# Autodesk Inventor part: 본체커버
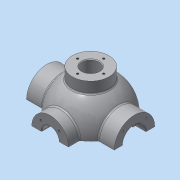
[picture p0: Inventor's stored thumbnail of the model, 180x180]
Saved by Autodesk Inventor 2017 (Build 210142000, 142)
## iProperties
Created: 2015-12
Part Number: 본체커버
Material: 알루미늄 6061
Document SubType Name: Modeling
Designer: mduedu
Density: 2.71 g/cm^3
Mass: 574.083 g
Surface Area: 451.737 cm^2
Volume: 211.839 cm^3
Appearance: 알루미늄 - 평지
Author: mduedu
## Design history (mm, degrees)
sketch "스케치1"
  geometry: L1 (-53, 0)-(53, 0); A1 r 53 centre (0, 0) between (53, 0) and (-53, 0); 2 further points
  constraints: 2 coincident, 2 end point, 2 point on circle, 1 centre point, 1 horizontal, 1 midpoint
  dimensions: "d0" = 53 radius of A1
revolve "회전1" sketch "스케치1" stored, may be unused: angle "d2" = 90 deg
feature "쉘1" dims "d11" = 10
node "작업 평면1"
sketch "스케치2"
  geometry: C1 r 31 at (0, 0); 1 further point
  constraints: 1 centre point, 1 coincident
  dimensions: "d4" = 62 diameter of C1
extrude "돌출1" join sketch "스케치2" stored distance "d5" = 10; taper "d6" = 0 deg
node "작업 평면2"
sketch "스케치3"
  geometry: C1 r 28 at (0, 0); 1 further point
  constraints: 1 centre point, 1 coincident
  dimensions: "d8" = 56 diameter of C1
extrude "돌출2" join sketch "스케치3" stored distance "d9" = 10; taper "d10" = 0 deg
hole "구멍1" diameter "d14" = 35; stored, may be unused: countersink angle "d18" = 90 deg, drill point angle "d20" = 0 deg; dims "d12" = 10, "d13" = 10, "d15" = 6, "d16" = 4, "d17" = 2, "d19" = 16
hole "구멍2" diameter "d23" = 27; stored, may be unused: countersink angle "d27" = 90 deg, drill point angle "d29" = 0 deg; dims "d21" = 10, "d22" = 10, "d24" = 6, "d25" = 4, "d26" = 2, "d28" = 16
fillet "모깎기1" dims "d30" = 0.3
hole "구멍3" diameter "d33" = 26; stored, may be unused: countersink angle "d37" = 90 deg, drill point angle "d39" = 0 deg; dims "d31" = 10, "d32" = 10, "d34" = 6, "d35" = 4, "d36" = 2, "d38" = 16
chamfer "모따기1" distance "d40" = 1; stored, may be unused: second distance "d41" = 2, angle "d42" = 45 deg
sketch "스케치4"
  geometry: L1 (0, 0)-(0, -25); L2 (0, 0)-(-17.678, -17.678); A1 r 25 centre (0, 0) between (-17.678, -17.678) and (0, -25); 1 further point
  constraints: 4 end point, 2 point on circle, 1 centre point, 1 coincident, 1 vertical
  dimensions: "d43" = 50 diameter of A1; "d47" = 45 deg angle of L1 L2
hole "구멍4" sketch "스케치4" at (-17.678, -17.678) diameter "d49" = 3.242; stored, may be unused: countersink angle "d53" = 90 deg, drill point angle "d55" = 118 deg; dims "d50" = 11, "d51" = 4, "d52" = 2, "d54" = 13
sketch "스케치5"
  geometry: L1 (0, 0)-(0, -20); L2 (0, 0)-(-14.142, -14.142); A1 r 20 centre (0, 0) between (0, -20) and (-14.142, -14.142); 2 further points
  constraints: 4 end point, 2 coincident, 2 point on circle, 1 centre point, 1 vertical
  dimensions: "d59" = 40 diameter of A1; "d65" = 45 deg angle of L1 L2
hole "구멍5" sketch "스케치5" at (-14.142, -14.142) diameter "d67" = 3.242; stored, may be unused: countersink angle "d71" = 90 deg, drill point angle "d73" = 118 deg; dims "d68" = 8, "d69" = 4, "d70" = 2, "d72" = 10
node "작업 평면3"
sketch "스케치6"
  geometry: C1 r 65 at (0, 0); 1 further point
  constraints: 1 centre point, 1 coincident
  dimensions: "d78" = 130 diameter of C1
extrude "돌출3" join sketch "스케치6" distance "d80" = 10; taper "d81" = 0 deg
sketch "스케치7"
  geometry: C1 r 20 at (0, 0); 1 further point
  constraints: 1 centre point, 1 coincident
  dimensions: "d82" = 40 diameter of C1
extrude "돌출4" join sketch "스케치7" stored distance "d84" = 10; taper "d85" = 0 deg
sketch "스케치8"
  geometry: 2 further points
  constraints: 1 coincident
hole "구멍6" sketch "스케치8" at (0, 0) diameter "d86" = 20; stored, may be unused: countersink angle "d90" = 90 deg, drill point angle "d92" = 118 deg; dims "d87" = 7, "d88" = 40, "d89" = 5, "d91" = 10
fillet "모깎기2" dims "d93" = 0.3
sketch "스케치9"
  geometry: L1 (65, -75)-(-65, -75) reference; L2 (-45, -75)-(-38.245, -36.692); A1 r 53 centre (0, 0) between (42.988, 31) and (42.988, -31) reference; 1 further point
  constraints: 2 end point, 1 point on circle, 1 point on line
  dimensions: "d94" = 45 horizontal distance of L2.start point (0, 0); "d95" = 80 deg angle of L2 L1
feature "리브1" sketch "스케치9" dims "d96" = 1, "d97" = 8, "d98" = 0, "d99" = 0, "d100" = 1, "d101" = 1
sketch "스케치10"
  geometry: L1 (0, 0)-(0, -55); L2 (0, 0)-(-38.891, -38.891); A1 r 55 centre (0, 0) between (0, -55) and (-38.891, -38.891); 2 further points
  constraints: 4 end point, 2 coincident, 2 point on circle, 1 centre point, 1 vertical
  dimensions: "d105" = 110 diameter of A1; "d107" = 45 deg angle of L1 L2
hole "구멍7" sketch "스케치10" at (-38.891, -38.891) diameter "d109" = 10; stored, may be unused: countersink angle "d113" = 90 deg, drill point angle "d115" = 118 deg; dims "d110" = 7, "d111" = 40, "d112" = 5, "d114" = 10
fillet "모깎기3" dims "d120" = 3
fillet "모깎기4" dims "d121" = 3, "d122" = 3
fillet "모깎기5" dims "d123" = 3
fillet "모깎기6" dims "d124" = 3
sketch "스케치11"
  geometry: C1 r 5 at (-38.891, 38.891) reference; C2 r 5 at (38.891, 38.891) reference; C3 r 5 at (38.891, -38.891) reference; C4 r 5 at (-38.891, -38.891) reference; C5 r 20 at (0, 0) reference; C6 r 65 at (0, 0) reference; 1 further point
  constraints: 3 other
feature "엠보싱1" sketch "스케치11" dims "d125" = 0.5, "d126" = 0
sketch "스케치12"
  geometry: L1 (0, 100)-(0, -100); L2 (0, 100)-(-150, 100); L3 (-150, 100)-(-150, -100); L4 (-150, -100)-(0, -100); 2 further points
  constraints: 8 end point, 3 perpendicular, 1 coincident, 1 midpoint, 1 vertical
  dimensions: "d127" = 200 distance of L2.end L3.end; "d129" = 150 distance of L3.end L1.end
extrude "돌출5" cut sketch "스케치12" stored distance "d130" = 10; taper "d131" = 0 deg
sketch "스케치13"
  geometry: C1 r 7 at (0, -53); A1 r 53 centre (0, 0) between (-42.113, -32.179) and (42.113, -32.179) reference; 1 further point
  constraints: 1 centre point, 1 point on circle
  dimensions: "d132" = 14 diameter of C1
extrude "돌출6" join sketch "스케치13" distance "d133" = 5; taper "d134" = 0 deg
sketch "스케치14"
  geometry: C1 r 7 at (0, 0) reference; 1 further point
extrude "돌출7" cut sketch "스케치14" stored distance "d135" = 5; taper "d136" = 0 deg
sketch "스케치15"
  geometry: C1 r 2.25 at (0, 53); A1 r 7 centre (0, 53) between (6.965, 52.302) and (-6.965, 52.302) reference; 1 further point
  constraints: 1 centre point, 1 coincident
  dimensions: "d139" = 4.5 diameter of C1
extrude "돌출8" cut sketch "스케치15" stored distance "d141" = 5; taper "d142" = 0 deg
fillet "모깎기7" dims "d143" = 3
fillet "모깎기8" dims "d144" = 1
fillet "모깎기9" dims "d145" = 1
fillet "모깎기10" dims "d146" = 1
node "작업 평면4"
sketch "스케치16"
  geometry: C1 r 28 at (0, 0); 1 further point
  constraints: 1 centre point, 1 coincident
  dimensions: "d148" = 56 diameter of C1
extrude "돌출9" join sketch "스케치16" stored distance "d150" = 5; taper "d151" = 0 deg
hole "구멍8" diameter "d154" = 26; stored, may be unused: countersink angle "d158" = 90 deg, drill point angle "d160" = 118 deg; dims "d152" = 10, "d153" = 10, "d155" = 6, "d156" = 4, "d157" = 2, "d159" = 8
sketch "스케치17" dims "d161" = 40
  geometry: 3 further points
  constraints: 2 vertical alignment, 1 coincident, 2 other
hole "구멍9" sketch "스케치17" at (0, 20) diameter "d163" = 3.242; stored, may be unused: countersink angle "d167" = 90 deg, drill point angle "d169" = 118 deg; dims "d164" = 8, "d165" = 4, "d166" = 2, "d168" = 10
fillet "모깎기11" dims "d173" = 3
chamfer "모따기2" distance "d174" = 1; stored, may be unused: second distance "d175" = 2, angle "d176" = 45 deg
node "솔리드1"
mirror "대칭1"
mirror "대칭2"
pattern_circular "원형 패턴1" dims angle "d57" = 360 deg
mirror "대칭3"
pattern_circular "원형 패턴2" dims angle "d75" = 360 deg
pattern_circular "원형 패턴3" dims angle "d103" = 360 deg
pattern_circular "원형 패턴4" dims angle "d118" = 360 deg
pattern_circular "원형 패턴5" dims angle "d171" = 360 deg
node "투영된 루프1"
other parameters: "d3" = 67, "d7" = 62, "d77" = -85, "d147" = 62
